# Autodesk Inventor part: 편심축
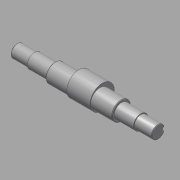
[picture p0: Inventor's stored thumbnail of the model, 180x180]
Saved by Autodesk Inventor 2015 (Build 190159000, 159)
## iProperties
Created: 2015-10
Part Number: 편심축
Document SubType Name: Modeling
Designer: mdu
Density: 7.86 g/cm^3
Material: 강철, 연강
Mass: 1327.93 g
Surface Area: 248.524 cm^2
Volume: 168.947 cm^3
Appearance: Steel
Author: mdu
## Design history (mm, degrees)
sketch "스케치1"
  geometry: L1 (-20.5, -41.331)-(-20.5, 32.669) reference; L2 (7.5, -30.031)-(7.5, 21.369) reference; L3 (135.5, -30.331)-(135.5, 21.669) reference; L4 (121.5, 21.369)-(121.5, -30.031) reference; L5 (184.5, -4.331)-(-57.5, -4.331); L6 (184.5, -4.331)-(184.5, 6.669); L7 (154.5, 8.169)-(121.5, 8.169); L8 (121.5, 8.169)-(121.5, 11.669); L9 (121.5, 11.669)-(7.5, 11.669); L10 (7.5, 11.669)-(7.5, 8.169); L11 (7.5, 8.169)-(-27.5, 8.169); L12 (-27.5, 8.169)-(-27.5, 6.669); L13 (-27.5, 6.669)-(-57.5, 6.669); L14 (-57.5, 6.669)-(-57.5, -4.331); L15 (154.5, 8.169)-(154.5, 6.669); L16 (154.5, 6.669)-(184.5, 6.669); C1 r 32.5 at (64.5, -4.331) reference; 1 further point
  constraints: 24 end point, 8 perpendicular, 5 point on line, 3 parallel, 2 collinear
  dimensions: "d1" = 25 diameter of L11 L5; "d2" = 32 diameter of L9 L5; "d3" = 22 diameter of L13 L5; "d4" = 35 distance of L10.end L11.end; "d5" = 30 distance of L12.end L13.end; "d15" = 33 distance of L7.start L7.end; "d26" = 30 distance of L15.end L6.end
revolve "회전1" sketch "스케치1" stored, may be unused: angle "d6" = 90 deg
node "작업 평면1"
sketch "스케치2"
  geometry: C1 r 16 at (0, 0) reference; C2 r 16 at (0, 0) reference; C3 r 20.75 at (0, 4); C4 r 16 at (0, 0) reference; 1 further point
  constraints: 1 centre point, 1 vertical alignment
  dimensions: "d8" = 41.5 diameter of C3; "d25" = 4 distance of C3.centre C1.centre
extrude "돌출1" join sketch "스케치2" stored distance "d9" = 40; taper "d10" = 0 deg
chamfer "모따기1" distance "d11" = 1; stored, may be unused: second distance "d12" = 2, angle "d13" = 45 deg
node "작업 평면2"
sketch "스케치3"
  geometry: L1 (-15, -10)-(-15, 10) reference; L2 (-15, 3)-(0, 3); L3 (0, -3)-(-15, -3); A1 r 3 centre (0, 0) between (0, -3) and (0, 3); 2 further points
  constraints: 4 end point, 2 perpendicular, 2 point on circle, 2 point on line, 2 tangent, 1 centre point, 1 horizontal alignment, 1 midpoint
  dimensions: "d16" = 18 dimension on A1 L1; "d17" = 6 distance between parallel lines of L3 L2
extrude "돌출2" cut sketch "스케치3" distance "d18" = 3.5; taper "d19" = 0 deg
node "작업 평면3"
node "솔리드1"
mirror "대칭1"
node "참조1"
node "참조2"
node "참조3"
node "참조4"
node "참조5"
node "투영된 루프1"
